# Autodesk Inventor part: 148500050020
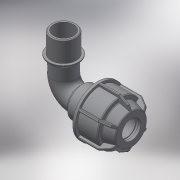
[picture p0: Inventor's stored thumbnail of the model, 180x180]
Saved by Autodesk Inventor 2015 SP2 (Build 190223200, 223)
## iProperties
Created: 2017-08
Part Number: 148500050020
Material: Generic
Description: PLASSON L.14 90° ELBOW MALE ADAPTOR (SILVER) 50-2"
Document SubType Name: Modeling
Designer: KIM
Density: 1 g/cm^3
Appearance: Default
Author: KIM
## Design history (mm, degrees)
derived "148500.ipt"
feature "Solid1::148500.ipt"
feature "Solid2::148500.ipt"
tag "TaggingFeature1"
body "Solid1"
body "Solid2"
other parameters: "d2" = 74, "d4" = 15 deg, "d5" = 48.84, "d6" = 16.1172, "d10" = 92, "d16" = 51, "d17" = 3.7, "d24" = 3.7, "d25" = 82.8, "d26" = 69, "d27" = 3.7, "d28" = 135 deg, "d29" = 2.22, "d31" = 2.5, "d46" = 150 deg, "d49" = 4.6, "d50" = 0, "d58" = 1.5, "d61" = 360 deg, "d63" = 48.5, "d94" = 77, "d96" = 65.5754, "d97" = 26, "d98" = 47.6912, "d99" = 55.73909, "d100" = 135 deg, "d108" = 2.5, "d112" = 33.8, "d113" = 104, "d114" = 75.48, "d115" = 55.73909, "d116" = 45 deg, "d117" = 0, "d118" = 0, "d119" = 59.614, "d120" = 26, "d121" = 71.5368, "d122" = 27.3, "d123" = 1, "R_" = 59.614, "E_" = 92, "A_" = 104, "l_" = 74, "l_2" = 26, "A_1" = 77
